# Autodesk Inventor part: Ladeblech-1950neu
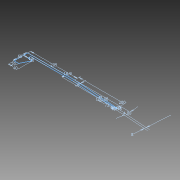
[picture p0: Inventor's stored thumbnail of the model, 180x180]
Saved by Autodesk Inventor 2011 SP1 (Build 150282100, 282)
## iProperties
Created: 2011-08
Part Number: Ladeblech-1950neu
Document SubType Name: Modeling
Designer: Inventor
Density: 2.71 g/cm^3
Material: Aluminium - 6061
Mass: 18347.1 g
Surface Area: 15023 cm^2
Volume: 6770.15 cm^3
Author: Inventor
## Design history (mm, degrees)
sketch "Skizze1"
  geometry: L1 (0, 0)-(0, -60); L2 (0, -60)-(20, -60); L3 (0, 0)-(205, 0); L4 (204.721, -8)-(20, -8); L5 (20, -20)-(20, -8); L6 (40, -20)-(20, -20); L7 (20, -60)-(40, -20); L8 (205, 0)-(405, -13.985); L9 (332, -16.9)-(204.721, -8); L10 (20, -8)-(20, -20); L11 (332, -16.9)-(405, -16.9); L12 (405, -16.9)-(405, -13.985)
  constraints: 24 end point, 2 perpendicular, 1 parallel, 1 vertical
  dimensions: "d0" = 60 distance of L1.start L1.end; "d1" = 20 distance of L1.end L2.end; "d2" = 205 distance of L1.start L3.end; "d3" = 8 distance between parallel lines of L4 L3; "d4" = 20 distance between parallel lines of L5 L1; "d6" = 12 distance between parallel lines of L6 L4; "d8" = 4 deg angle of L8 L3; "d9" = 200 horizontal distance of L8.end L3.end; "d10" = 8 distance between parallel lines of L9 L8; "d160" = 40 distance from line of L1 L6.start; "d162" = 73 distance of L9.start L11.end; "d163" = 94 deg angle of L12 L8; "d164" = 176 deg angle of L11 L9; "d166" = 2.91488 distance of L12.start L8.end; "d167" = 16.90024 distance from line of L1.start L11
node "Volumenkörper1"
